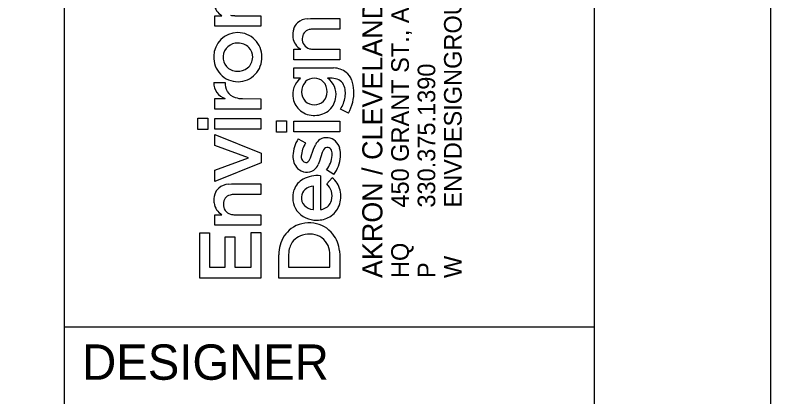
# Model space of a CAD drawing. Extents: x -0.2 to 34, y 0 to 22.
# Drawn here: x 31.86 to 34, y 2.302 to 3.382 of the extents above; entities that cross this region are included whole.
import ezdxf

# ---------------------------------------------------------------- set-up
doc = ezdxf.new("R2010")
doc.units = 0
for name, color, linetype in [('SH_Border', 7, 'Continuous'), ('SH_Cut_Line', 7, 'Continuous'), ('SH_Data', 7, 'Continuous')]:
    doc.layers.add(name, color=color, linetype=linetype)

msp = doc.modelspace()

# ---------------------------------------------------------------- linework, layer by layer
at = {"layer": 'SH_Border'}
for p, q in [((32, 0.5), (32, 21.5)), ((32, 2.5), (33.5, 2.5))]:
    msp.add_line(p, q, dxfattribs=at)
msp.add_lwpolyline([(1.5, 21.5), (33.5, 21.5), (33.5, 0.5), (1.5, 0.5)], close=True, dxfattribs=at)
at = {"layer": 'SH_Cut_Line'}
msp.add_lwpolyline([(0, 0), (34, 0), (34, 22), (0, 22)], close=True, dxfattribs=at)
at = {"layer": 'SH_Data'}
for p, q in [((32.4254, 3.3509), (32.4254, 3.3807)), ((32.4254, 3.3807), (32.4455, 3.3807)), ((32.4822, 3.3807), (32.5557, 3.3807)), ((32.5557, 3.3807), (32.5557, 3.351)), ((32.6878, 3.3722), (32.6963, 3.3727)), ((32.6963, 3.3727), (32.7792, 3.3727)), ((32.7792, 3.3727), (32.7792, 3.3429)), ((32.5557, 3.351), (32.4254, 3.3509)), ((32.7792, 3.3429), (32.7048, 3.3428)), ((32.6489, 3.2557), (32.6489, 3.2855)), ((32.6489, 3.2855), (32.669, 3.2855)), ((32.7057, 3.2855), (32.7791, 3.2855)), ((32.7791, 3.2855), (32.7792, 3.2558)), ((32.7792, 3.2558), (32.6489, 3.2557)), ((32.6489, 3.2034), (32.6489, 3.2332)), ((32.6489, 3.2332), (32.7524, 3.2332)), ((32.7524, 3.2332), (32.7619, 3.2329)), ((32.423, 3.1919), (32.4545, 3.1919)), ((32.6684, 3.2034), (32.6489, 3.2034)), ((32.7576, 3.2036), (32.7449, 3.2036)), ((32.4254, 3.1159), (32.4254, 3.1458)), ((32.4254, 3.1458), (32.4547, 3.1458)), ((32.5041, 3.1458), (32.5557, 3.1457)), ((32.5557, 3.1457), (32.5556, 3.1159)), ((32.5556, 3.1159), (32.4254, 3.1159)), ((32.8036, 3.1049), (32.7812, 3.116)), ((32.3771, 3.0582), (32.3771, 3.0903)), ((32.3771, 3.0903), (32.4054, 3.0903)), ((32.4054, 3.0903), (32.4054, 3.0582)), ((32.4254, 3.0594), (32.4254, 3.0893)), ((32.4254, 3.0893), (32.5557, 3.0893)), ((32.5557, 3.0893), (32.5557, 3.0594)), ((32.6005, 3.0511), (32.6005, 3.0832)), ((32.6005, 3.0832), (32.6289, 3.0832)), ((32.6289, 3.0832), (32.6289, 3.0511)), ((32.6489, 3.0523), (32.6489, 3.0822)), ((32.6489, 3.0822), (32.7792, 3.0822)), ((32.7792, 3.0822), (32.7792, 3.0523)), ((32.4054, 3.0582), (32.3771, 3.0582)), ((32.5557, 3.0594), (32.4254, 3.0594)), ((32.4254, 3.0133), (32.4254, 3.0446)), ((32.4254, 3.0446), (32.5567, 2.9913)), ((32.6289, 3.0511), (32.6005, 3.0511)), ((32.7792, 3.0523), (32.6489, 3.0523)), ((32.6615, 3.0321), (32.6827, 3.0203)), ((32.5212, 2.978), (32.4254, 3.0133)), ((32.6967, 2.9787), (32.7048, 3.0026)), ((32.7048, 3.0026), (32.7104, 3.0153)), ((32.7334, 3.001), (32.7298, 2.9933)), ((32.4254, 2.9429), (32.5212, 2.978)), ((32.5567, 2.9913), (32.5567, 2.9644)), ((32.693, 2.9712), (32.6967, 2.9787)), ((32.7298, 2.9933), (32.7221, 2.9688)), ((32.5567, 2.9644), (32.4254, 2.9109)), ((32.7221, 2.9688), (32.7182, 2.9592)), ((32.4254, 2.9109), (32.4254, 2.9429)), ((32.7621, 2.9314), (32.742, 2.9447)), ((32.7245, 2.9275), (32.7246, 2.8319)), ((32.7423, 2.9046), (32.7577, 2.922)), ((32.4644, 2.904), (32.4729, 2.9044)), ((32.4729, 2.9044), (32.5557, 2.9044)), ((32.5557, 2.9044), (32.5557, 2.8746)), ((32.7049, 2.8318), (32.7049, 2.8983)), ((32.5557, 2.8746), (32.4814, 2.8746)), ((32.7036, 2.8317), (32.7049, 2.8318)), ((32.4254, 2.7875), (32.4254, 2.8173)), ((32.4254, 2.8173), (32.4455, 2.8173)), ((32.4822, 2.8173), (32.5557, 2.8173)), ((32.5557, 2.8173), (32.5557, 2.7876)), ((32.5557, 2.7876), (32.4254, 2.7875)), ((32.383, 2.6379), (32.383, 2.766)), ((32.383, 2.766), (32.4101, 2.766)), ((32.4101, 2.766), (32.4101, 2.6683)), ((32.5286, 2.6683), (32.5286, 2.7672)), ((32.5286, 2.7672), (32.5557, 2.7672)), ((32.5557, 2.7672), (32.5557, 2.6379)), ((32.455, 2.6683), (32.455, 2.7549)), ((32.455, 2.7549), (32.4822, 2.7549)), ((32.4822, 2.7549), (32.4822, 2.6683)), ((32.6064, 2.638), (32.6064, 2.704)), ((32.6347, 2.7118), (32.6341, 2.7023)), ((32.6341, 2.7023), (32.6341, 2.6684)), ((32.7515, 2.6683), (32.7515, 2.7024)), ((32.7785, 2.715), (32.7792, 2.7021)), ((32.7792, 2.7021), (32.7792, 2.638)), ((32.4101, 2.6683), (32.455, 2.6683)), ((32.4822, 2.6683), (32.5286, 2.6683)), ((32.6341, 2.6684), (32.7515, 2.6683)), ((32.5557, 2.6379), (32.383, 2.6379)), ((32.7792, 2.638), (32.6064, 2.638))]:
    msp.add_line(p, q, dxfattribs=at)
for points in [[(32.4254, 3.3509), (32.4254, 3.3807), (32.4455, 3.3807)], [(32.4822, 3.3807), (32.5557, 3.3807), (32.5557, 3.351), (32.4254, 3.3509)], [(32.6878, 3.3722), (32.6963, 3.3727), (32.7792, 3.3727), (32.7792, 3.3429), (32.7048, 3.3428)], [(32.6489, 3.2557), (32.6489, 3.2855), (32.669, 3.2855)], [(32.7057, 3.2855), (32.7791, 3.2855), (32.7792, 3.2558), (32.6489, 3.2557)], [(32.6684, 3.2034), (32.6489, 3.2034), (32.6489, 3.2332), (32.7524, 3.2332), (32.7619, 3.2329)], [(32.423, 3.1919), (32.4545, 3.1919)], [(32.7576, 3.2036), (32.7449, 3.2036)], [(32.4254, 3.1159), (32.4254, 3.1458), (32.4547, 3.1458)], [(32.5041, 3.1458), (32.5557, 3.1457), (32.5556, 3.1159), (32.4254, 3.1159)], [(32.8036, 3.1049), (32.7812, 3.116)], [(32.6615, 3.0321), (32.6827, 3.0203)], [(32.693, 2.9712), (32.6967, 2.9787), (32.7048, 3.0026), (32.7104, 3.0153)], [(32.7334, 3.001), (32.7298, 2.9933), (32.7221, 2.9688), (32.7182, 2.9592)], [(32.7621, 2.9314), (32.742, 2.9447)], [(32.7245, 2.9275), (32.7246, 2.8319)], [(32.7423, 2.9046), (32.7577, 2.922)], [(32.4644, 2.904), (32.4729, 2.9044), (32.5557, 2.9044), (32.5557, 2.8746), (32.4814, 2.8746)], [(32.7036, 2.8317), (32.7049, 2.8318), (32.7049, 2.8983)], [(32.4254, 2.7875), (32.4254, 2.8173), (32.4455, 2.8173)], [(32.4822, 2.8173), (32.5557, 2.8173), (32.5557, 2.7876), (32.4254, 2.7875)], [(32.7785, 2.715), (32.7792, 2.7021), (32.7792, 2.638), (32.6064, 2.638)], [(32.6064, 2.638), (32.6064, 2.704)], [(32.6347, 2.7118), (32.6341, 2.7023), (32.6341, 2.6684), (32.7515, 2.6683), (32.7515, 2.7024)]]:
    msp.add_lwpolyline(points, dxfattribs=at)
for points in [[(32.3771, 3.0582), (32.3771, 3.0903), (32.4054, 3.0903), (32.4054, 3.0582)], [(32.4254, 3.0594), (32.4254, 3.0893), (32.5557, 3.0893), (32.5557, 3.0594)], [(32.6005, 3.0511), (32.6005, 3.0832), (32.6289, 3.0832), (32.6289, 3.0511)], [(32.6489, 3.0523), (32.6489, 3.0822), (32.7792, 3.0822), (32.7792, 3.0523)], [(32.4254, 2.9109), (32.4254, 2.9429), (32.5212, 2.978), (32.4254, 3.0133), (32.4254, 3.0446), (32.5567, 2.9913), (32.5567, 2.9644)], [(32.383, 2.6379), (32.383, 2.766), (32.4101, 2.766), (32.4101, 2.6683), (32.455, 2.6683), (32.455, 2.7549), (32.4822, 2.7549), (32.4822, 2.6683), (32.5286, 2.6683), (32.5286, 2.7672), (32.5557, 2.7672), (32.5557, 2.6379)]]:
    msp.add_lwpolyline(points, close=True, dxfattribs=at)
for centre, radius, start, end in [((32.4703, 3.4214), 0.0476, 188.9646, 238.6987), ((32.4703, 3.4214), 0.0476, 188.9646, 238.6987), ((32.4818, 3.4229), 0.0421, 254.0891, 270.5284), ((32.4818, 3.4229), 0.0421, 254.0891, 270.5284), ((32.6869, 3.3309), 0.0402, 132.2238, 161.6823), ((32.6869, 3.3309), 0.0402, 132.2238, 161.6823), ((32.6922, 3.3225), 0.0499, 94.9706, 130.2248), ((32.6922, 3.3225), 0.0499, 94.9706, 130.2248), ((32.7022, 3.3264), 0.056, 162.274, 187.7917), ((32.7022, 3.3264), 0.056, 162.274, 187.7917), ((32.6983, 3.3169), 0.025, 103.6868, 182.214), ((32.6983, 3.3169), 0.025, 103.6868, 182.214), ((32.7045, 3.2968), 0.046, 89.6051, 105.3303), ((32.7045, 3.2968), 0.046, 89.6051, 105.3303), ((32.4901, 3.2654), 0.0674, 89.8476, 179.6405), ((32.4901, 3.2654), 0.0674, 89.8476, 179.6405), ((32.4906, 3.2647), 0.0681, 359.5401, 90.2114), ((32.4906, 3.2647), 0.0681, 359.5401, 90.2114), ((32.6937, 3.3262), 0.0476, 188.9646, 238.6987), ((32.6937, 3.3262), 0.0476, 188.9646, 238.6987), ((32.4892, 3.2626), 0.0404, 87.0481, 175.5726), ((32.4892, 3.2626), 0.0404, 87.0481, 175.5726), ((32.492, 3.26), 0.043, 45.8426, 90.9801), ((32.492, 3.26), 0.043, 45.8426, 90.9801), ((32.7008, 3.3138), 0.0276, 175.5844, 255.1382), ((32.7008, 3.3138), 0.0276, 175.5844, 255.1382), ((32.4946, 3.2642), 0.0382, 357.8857, 44.159), ((32.4946, 3.2642), 0.0382, 357.8857, 44.159), ((32.7053, 3.3277), 0.0421, 254.0891, 270.5284), ((32.7053, 3.3277), 0.0421, 254.0891, 270.5284), ((32.4908, 3.2621), 0.0682, 176.8344, 270.4038), ((32.4908, 3.2621), 0.0682, 176.8344, 270.4038), ((32.4873, 3.2625), 0.0385, 175.1538, 221.1471), ((32.4873, 3.2625), 0.0385, 175.1538, 221.1471), ((32.4912, 3.2614), 0.0675, 270.0624, 2.3776), ((32.4912, 3.2614), 0.0675, 270.0624, 2.3776), ((32.4945, 3.2632), 0.0383, 308.2894, 359.4347), ((32.4945, 3.2632), 0.0383, 308.2894, 359.4347), ((32.4892, 3.2661), 0.0423, 223.0999, 268.8089), ((32.4892, 3.2661), 0.0423, 223.0999, 268.8089), ((32.491, 3.2679), 0.0442, 266.5651, 308.0608), ((32.491, 3.2679), 0.0442, 266.5651, 308.0608), ((32.7591, 3.1679), 0.065, 53.4034, 87.4906), ((32.7591, 3.1679), 0.065, 53.4034, 87.4906), ((32.7652, 3.1804), 0.0514, 21.6075, 50.5577), ((32.7652, 3.1804), 0.0514, 21.6075, 50.5577), ((32.4662, 3.1888), 0.0433, 175.8731, 216.3475), ((32.4662, 3.1888), 0.0433, 175.8731, 216.3475), ((32.5009, 3.1895), 0.0464, 176.9688, 209.6064), ((32.5009, 3.1895), 0.0464, 176.9688, 209.6064), ((32.7029, 3.1581), 0.0569, 127.3748, 192.2247), ((32.7029, 3.1581), 0.0569, 127.3748, 192.2247), ((32.7114, 3.166), 0.0401, 137.4674, 182.3324), ((32.7114, 3.166), 0.0401, 137.4674, 182.3324), ((32.7069, 3.1693), 0.0346, 88.473, 136.4256), ((32.7069, 3.1693), 0.0346, 88.473, 136.4256), ((32.7081, 3.1696), 0.0342, 44.2719, 90.4762), ((32.7081, 3.1696), 0.0342, 44.2719, 90.4762), ((32.7037, 3.166), 0.04, 358.5714, 43.5376), ((32.7037, 3.166), 0.04, 358.5714, 43.5376), ((32.7142, 3.1583), 0.0547, 352.1125, 55.923), ((32.7142, 3.1583), 0.0547, 352.1125, 55.923), ((32.7567, 3.1572), 0.0463, 65.0169, 88.8011), ((32.7567, 3.1572), 0.0463, 65.0169, 88.8011), ((32.7626, 3.1716), 0.0309, 26.2681, 63.803), ((32.7626, 3.1716), 0.0309, 26.2681, 63.803), ((32.7307, 3.1671), 0.0884, 1.1514, 21.3627), ((32.7307, 3.1671), 0.0884, 1.1514, 21.3627), ((32.7357, 3.1615), 0.0595, 349.3073, 23.4307), ((32.7357, 3.1615), 0.0595, 349.3073, 23.4307), ((32.7054, 3.1624), 0.1138, 329.6388, 3.26), ((32.7054, 3.1624), 0.1138, 329.6388, 3.26), ((32.4747, 3.1972), 0.0551, 218.0981, 248.7907), ((32.4747, 3.1972), 0.0551, 218.0981, 248.7907), ((32.4951, 3.1881), 0.0408, 211.9447, 253.2028), ((32.4951, 3.1881), 0.0408, 211.9447, 253.2028), ((32.5047, 3.2165), 0.0707, 252.4655, 269.573), ((32.5047, 3.2165), 0.0707, 252.4655, 269.573), ((32.7046, 3.157), 0.0584, 190.7518, 231.2892), ((32.7046, 3.157), 0.0584, 190.7518, 231.2892), ((32.7065, 3.1637), 0.0351, 178.8821, 271.0837), ((32.7065, 3.1637), 0.0351, 178.8821, 271.0837), ((32.7082, 3.164), 0.0355, 268.2788, 1.5502), ((32.7082, 3.164), 0.0355, 268.2788, 1.5502), ((32.7099, 3.1571), 0.0589, 313.742, 353.8554), ((32.7099, 3.1571), 0.0589, 313.742, 353.8554), ((32.7074, 3.1633), 0.0877, 327.3149, 351.5748), ((32.7074, 3.1633), 0.0877, 327.3149, 351.5748), ((32.7063, 3.1611), 0.0627, 232.4606, 272.5902), ((32.7063, 3.1611), 0.0627, 232.4606, 272.5902), ((32.7095, 3.159), 0.0605, 269.6361, 312.7088), ((32.7095, 3.159), 0.0605, 269.6361, 312.7088), ((32.7364, 2.9826), 0.0897, 146.531, 178.7571), ((32.7364, 2.9826), 0.0897, 146.531, 178.7571), ((32.7452, 2.9789), 0.0749, 146.5112, 176.9101), ((32.7452, 2.9789), 0.0749, 146.5112, 176.9101), ((32.7466, 2.9971), 0.0405, 125.5118, 153.4159), ((32.7466, 2.9971), 0.0405, 125.5118, 153.4159), ((32.7406, 3.0026), 0.0326, 80.1719, 122.5197), ((32.7406, 3.0026), 0.0326, 80.1719, 122.5197), ((32.7428, 2.9982), 0.0367, 47.7934, 84.6892), ((32.7428, 2.9982), 0.0367, 47.7934, 84.6892), ((32.7379, 2.9946), 0.0427, 14.9966, 46.2063), ((32.7379, 2.9946), 0.0427, 14.9966, 46.2063), ((32.7438, 2.9963), 0.0114, 76.6609, 155.7053), ((32.7438, 2.9963), 0.0114, 76.6609, 155.7053), ((32.744, 2.9951), 0.0126, 21.5098, 78.5262), ((32.744, 2.9951), 0.0126, 21.5098, 78.5262), ((32.7259, 2.9877), 0.0321, 354.5726, 22.068), ((32.7259, 2.9877), 0.0321, 354.5726, 22.068), ((32.7104, 2.9867), 0.0712, 355.8306, 15.3914), ((32.7104, 2.9867), 0.0712, 355.8306, 15.3914), ((32.6967, 2.9824), 0.0501, 177.5366, 222.7932), ((32.6967, 2.9824), 0.0501, 177.5366, 222.7932), ((32.6931, 2.9823), 0.0228, 178.4747, 211.0868), ((32.6931, 2.9823), 0.0228, 178.4747, 211.0868), ((32.6825, 2.9915), 0.0757, 321.811, 354.7969), ((32.6825, 2.9915), 0.0757, 321.811, 354.7969), ((32.6895, 2.9882), 0.0922, 321.9777, 355.8738), ((32.6895, 2.9882), 0.0922, 321.9777, 355.8738), ((32.6833, 2.9767), 0.0115, 212.2368, 268.3777), ((32.6833, 2.9767), 0.0115, 212.2368, 268.3777), ((32.6834, 2.9759), 0.0107, 267.716, 333.7337), ((32.6834, 2.9759), 0.0107, 267.716, 333.7337), ((32.681, 2.9758), 0.0408, 308.0877, 335.9874), ((32.681, 2.9758), 0.0408, 308.0877, 335.9874), ((32.686, 2.9753), 0.0375, 225.9854, 302.4797), ((32.686, 2.9753), 0.0375, 225.9854, 302.4797), ((32.7024, 2.8691), 0.0558, 118.8308, 160.6244), ((32.7024, 2.8691), 0.0558, 118.8308, 160.6244), ((32.7152, 2.8441), 0.0838, 83.615, 118.2876), ((32.7152, 2.8441), 0.0838, 83.615, 118.2876), ((32.7174, 2.8717), 0.0644, 13.5336, 51.3615), ((32.7174, 2.8717), 0.0644, 13.5336, 51.3615), ((32.4635, 2.8626), 0.0402, 132.2219, 161.6818), ((32.4635, 2.8626), 0.0402, 132.2219, 161.6818), ((32.4687, 2.8543), 0.0499, 94.9696, 130.2225), ((32.4687, 2.8543), 0.0499, 94.9696, 130.2225), ((32.7079, 2.8561), 0.0424, 94.008, 130.8817), ((32.7079, 2.8561), 0.0424, 94.008, 130.8817), ((32.7038, 2.8656), 0.0549, 19.0357, 45.4406), ((32.7038, 2.8656), 0.0549, 19.0357, 45.4406), ((32.4787, 2.8582), 0.056, 162.2736, 187.7919), ((32.4787, 2.8582), 0.056, 162.2736, 187.7919), ((32.4748, 2.8487), 0.025, 103.6865, 182.2187), ((32.4748, 2.8487), 0.025, 103.6865, 182.2187), ((32.4811, 2.8286), 0.046, 89.6049, 105.3284), ((32.4811, 2.8286), 0.046, 89.6049, 105.3284), ((32.7104, 2.8661), 0.0644, 160.5201, 215.7831), ((32.7104, 2.8661), 0.0644, 160.5201, 215.7831), ((32.7017, 2.865), 0.0311, 175.0013, 223.283), ((32.7017, 2.865), 0.0311, 175.0013, 223.283), ((32.7005, 2.8663), 0.0298, 132.9851, 177.179), ((32.7005, 2.8663), 0.0298, 132.9851, 177.179), ((32.7107, 2.8697), 0.047, 344.6059, 17.007), ((32.7107, 2.8697), 0.047, 344.6059, 17.007), ((32.7064, 2.8692), 0.0758, 339.3542, 13.3785), ((32.7064, 2.8692), 0.0758, 339.3542, 13.3785), ((32.4703, 2.858), 0.0476, 188.962, 238.7037), ((32.4703, 2.858), 0.0476, 188.962, 238.7037), ((32.4773, 2.8456), 0.0276, 175.5854, 255.1439), ((32.4773, 2.8456), 0.0276, 175.5854, 255.1439), ((32.7224, 2.8671), 0.035, 288.0077, 343.5508), ((32.7224, 2.8671), 0.035, 288.0077, 343.5508), ((32.7125, 2.8705), 0.0687, 217.7452, 271.6543), ((32.7125, 2.8705), 0.0687, 217.7452, 271.6543), ((32.7089, 2.8736), 0.0423, 225.0619, 262.7974), ((32.7089, 2.8736), 0.0423, 225.0619, 262.7974), ((32.7247, 2.8522), 0.0202, 269.7003, 294.8711), ((32.7247, 2.8522), 0.0202, 269.7003, 294.8711), ((32.7189, 2.8652), 0.0626, 300.9427, 338.7323), ((32.7189, 2.8652), 0.0626, 300.9427, 338.7323), ((32.4818, 2.8595), 0.0422, 254.0916, 270.5284), ((32.4818, 2.8595), 0.0422, 254.0916, 270.5284), ((32.7155, 2.8724), 0.0706, 269.2048, 300.3341), ((32.7155, 2.8724), 0.0706, 269.2048, 300.3341), ((32.6923, 2.7079), 0.0864, 81.194, 125.9984), ((32.6923, 2.7079), 0.0864, 81.194, 125.9984), ((32.6946, 2.7113), 0.0827, 37.8521, 82.402), ((32.6946, 2.7113), 0.0827, 37.8521, 82.402), ((32.6939, 2.7089), 0.0865, 127.2362, 165.148), ((32.6939, 2.7089), 0.0865, 127.2362, 165.148), ((32.6928, 2.6986), 0.0639, 55.6727, 107.2093), ((32.6928, 2.6986), 0.0639, 55.6727, 107.2093), ((32.6859, 2.7057), 0.0931, 5.7333, 37.304), ((32.6859, 2.7057), 0.0931, 5.7333, 37.304), ((32.6889, 2.7078), 0.054, 106.1881, 157.3861), ((32.6889, 2.7078), 0.054, 106.1881, 157.3861), ((32.6929, 2.705), 0.0587, 357.4662, 52.2665), ((32.6929, 2.705), 0.0587, 357.4662, 52.2665), ((32.7143, 2.7028), 0.1078, 164.7861, 179.3704), ((32.7143, 2.7028), 0.1078, 164.7861, 179.3704), ((32.6983, 2.7039), 0.0641, 157.3571, 172.9275), ((32.6983, 2.7039), 0.0641, 157.3571, 172.9275)]:
    msp.add_arc(centre, radius, start, end, dxfattribs=at)

# ---------------------------------------------------------------- texts
for s, height, p in [('450 GRANT ST., AKRON, OH  44311', 0.049846, (32.9749, 2.8374)), ('AKRON / CLEVELAND / COLUMBUS', 0.056969, (32.9001, 2.638)), ('ENVDESIGNGROUP.COM', 0.049846, (33.1244, 2.8374)), ('330.375.1390', 0.049846, (33.0497, 2.8374)), ('HQ ', 0.04985, (32.9749, 2.638)), ('W', 0.0498, (33.1244, 2.638)), ('P', 0.0498, (33.0497, 2.638))]:
    msp.add_text(s, height=height, rotation=90, dxfattribs=at).set_placement(p)
msp.add_text('DESIGNER', height=0.1, dxfattribs=at).set_placement((32.05, 2.35))

doc.saveas('drawing.dxf')
